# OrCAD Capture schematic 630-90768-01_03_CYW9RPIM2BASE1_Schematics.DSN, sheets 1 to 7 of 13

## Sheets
1 08. USB-UART Bridge: size B; title: CYW9RPIM2BASE1; rev: 3.0; note: 630-90768-01
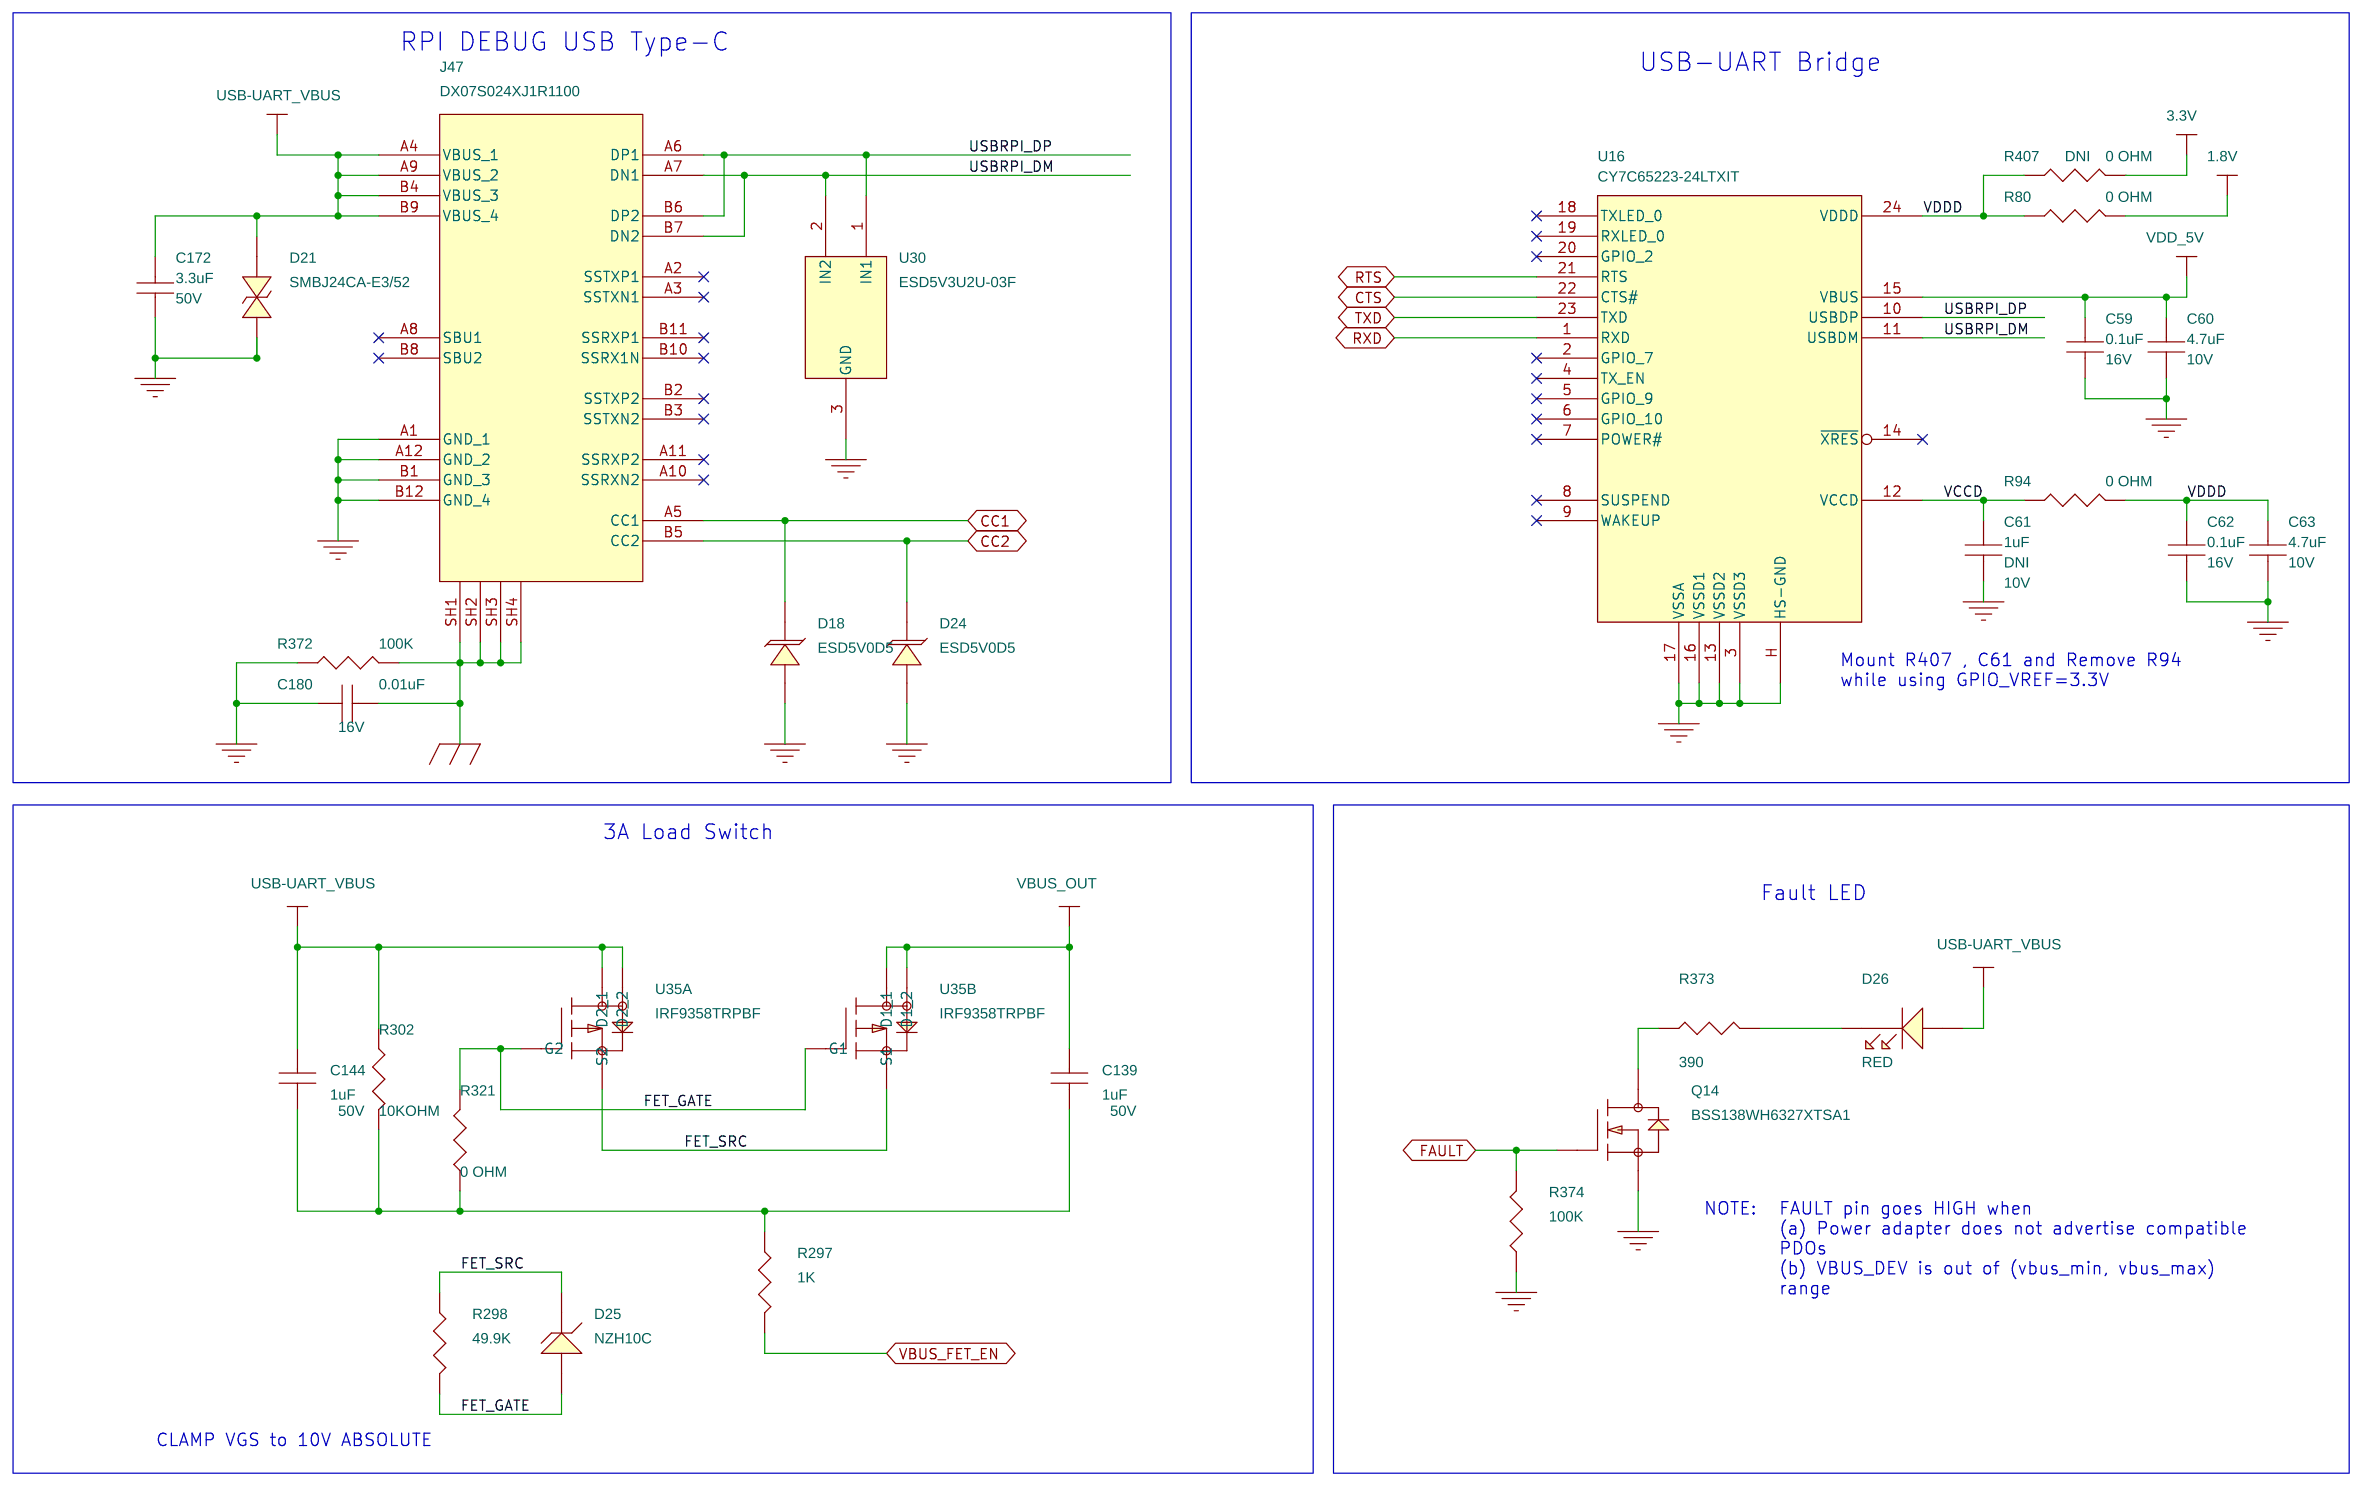
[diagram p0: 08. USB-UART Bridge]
2 09. Type-C BCR Controller: size B
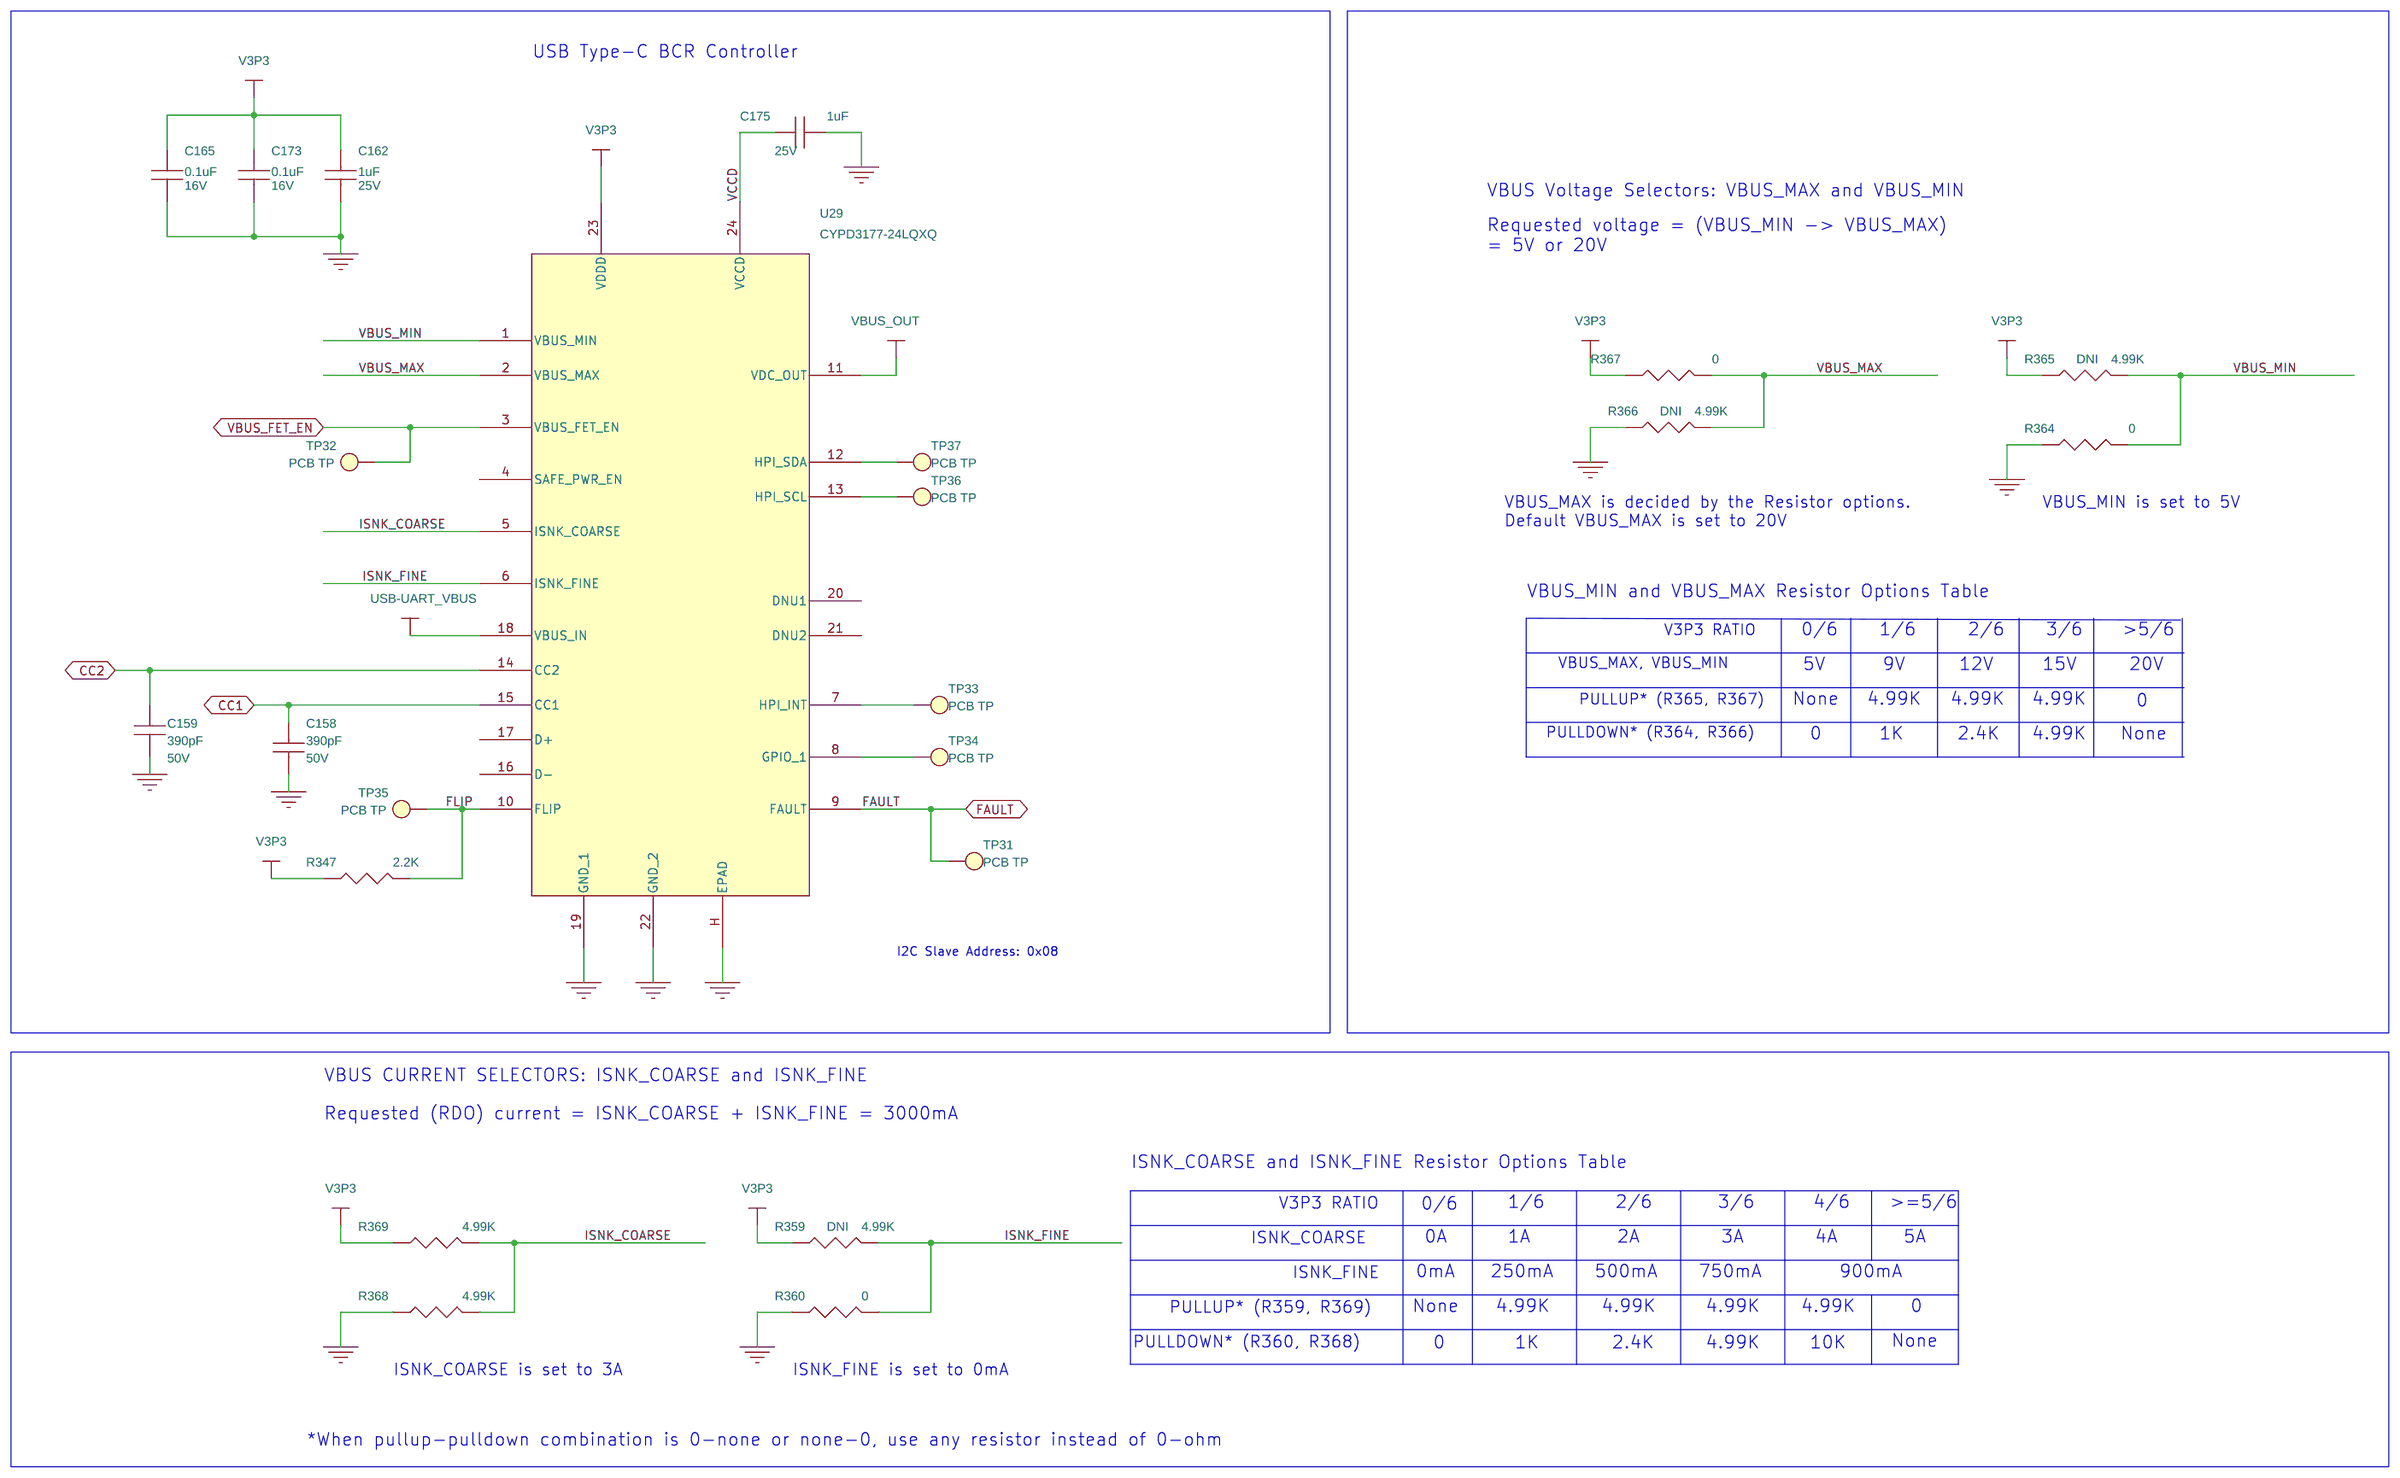
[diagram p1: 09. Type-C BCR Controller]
3 10. Audio Out: size A4
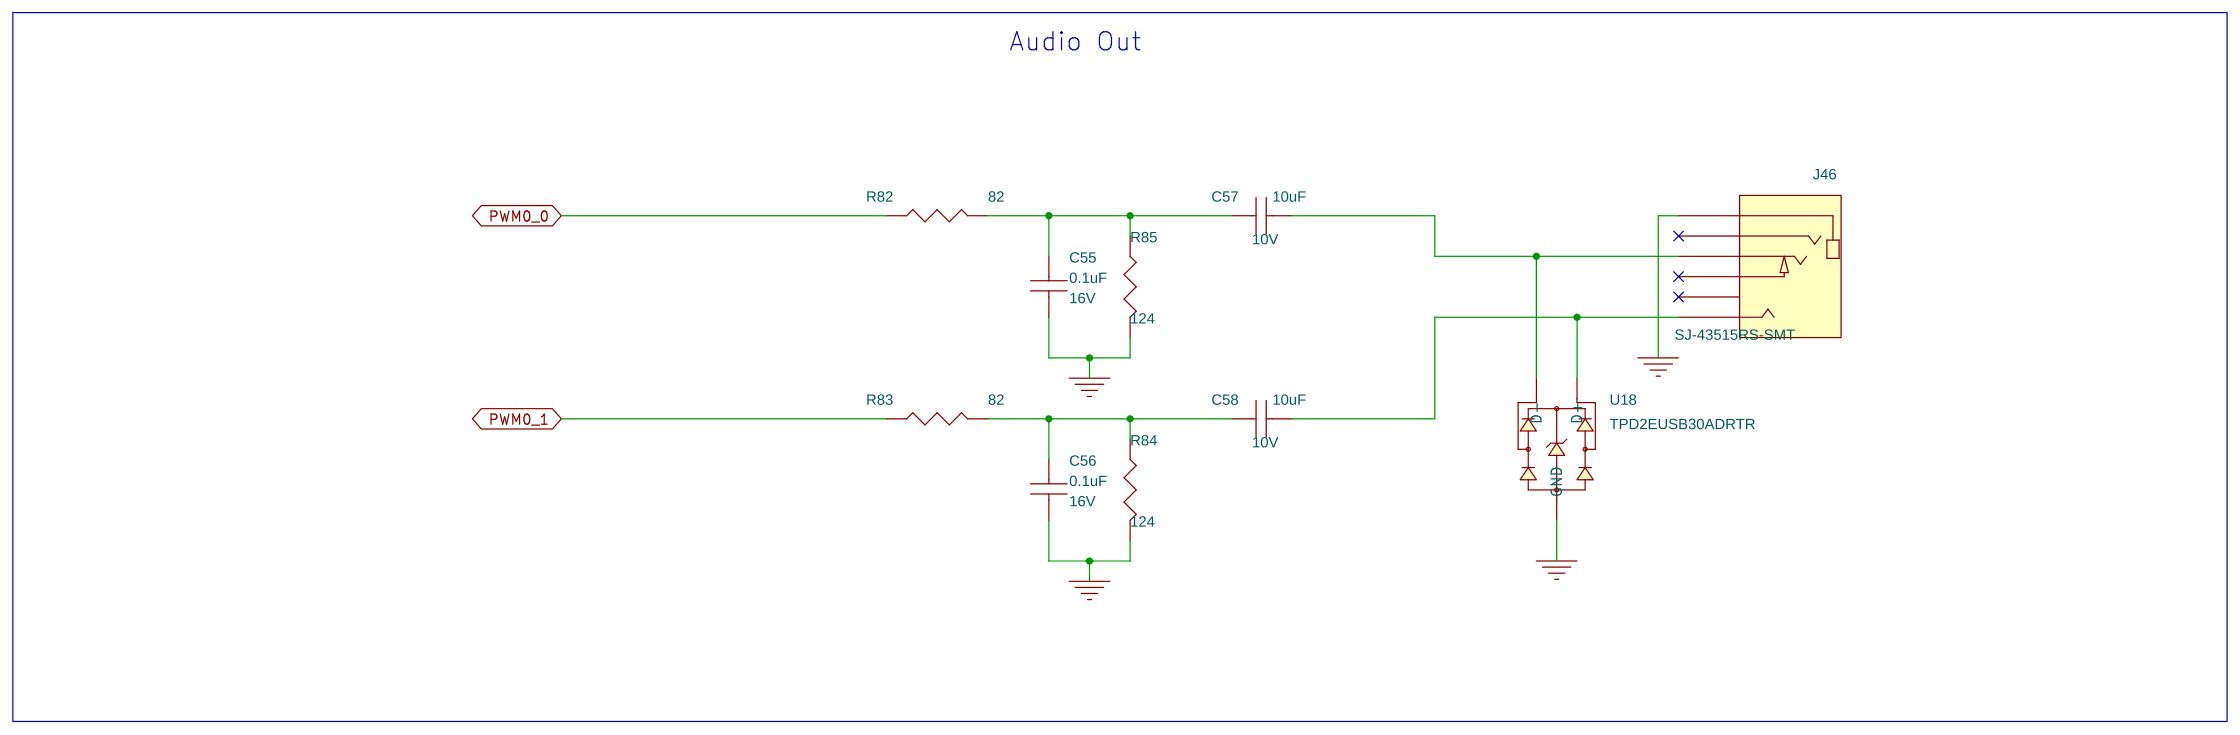
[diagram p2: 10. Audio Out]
4 01. Title Page
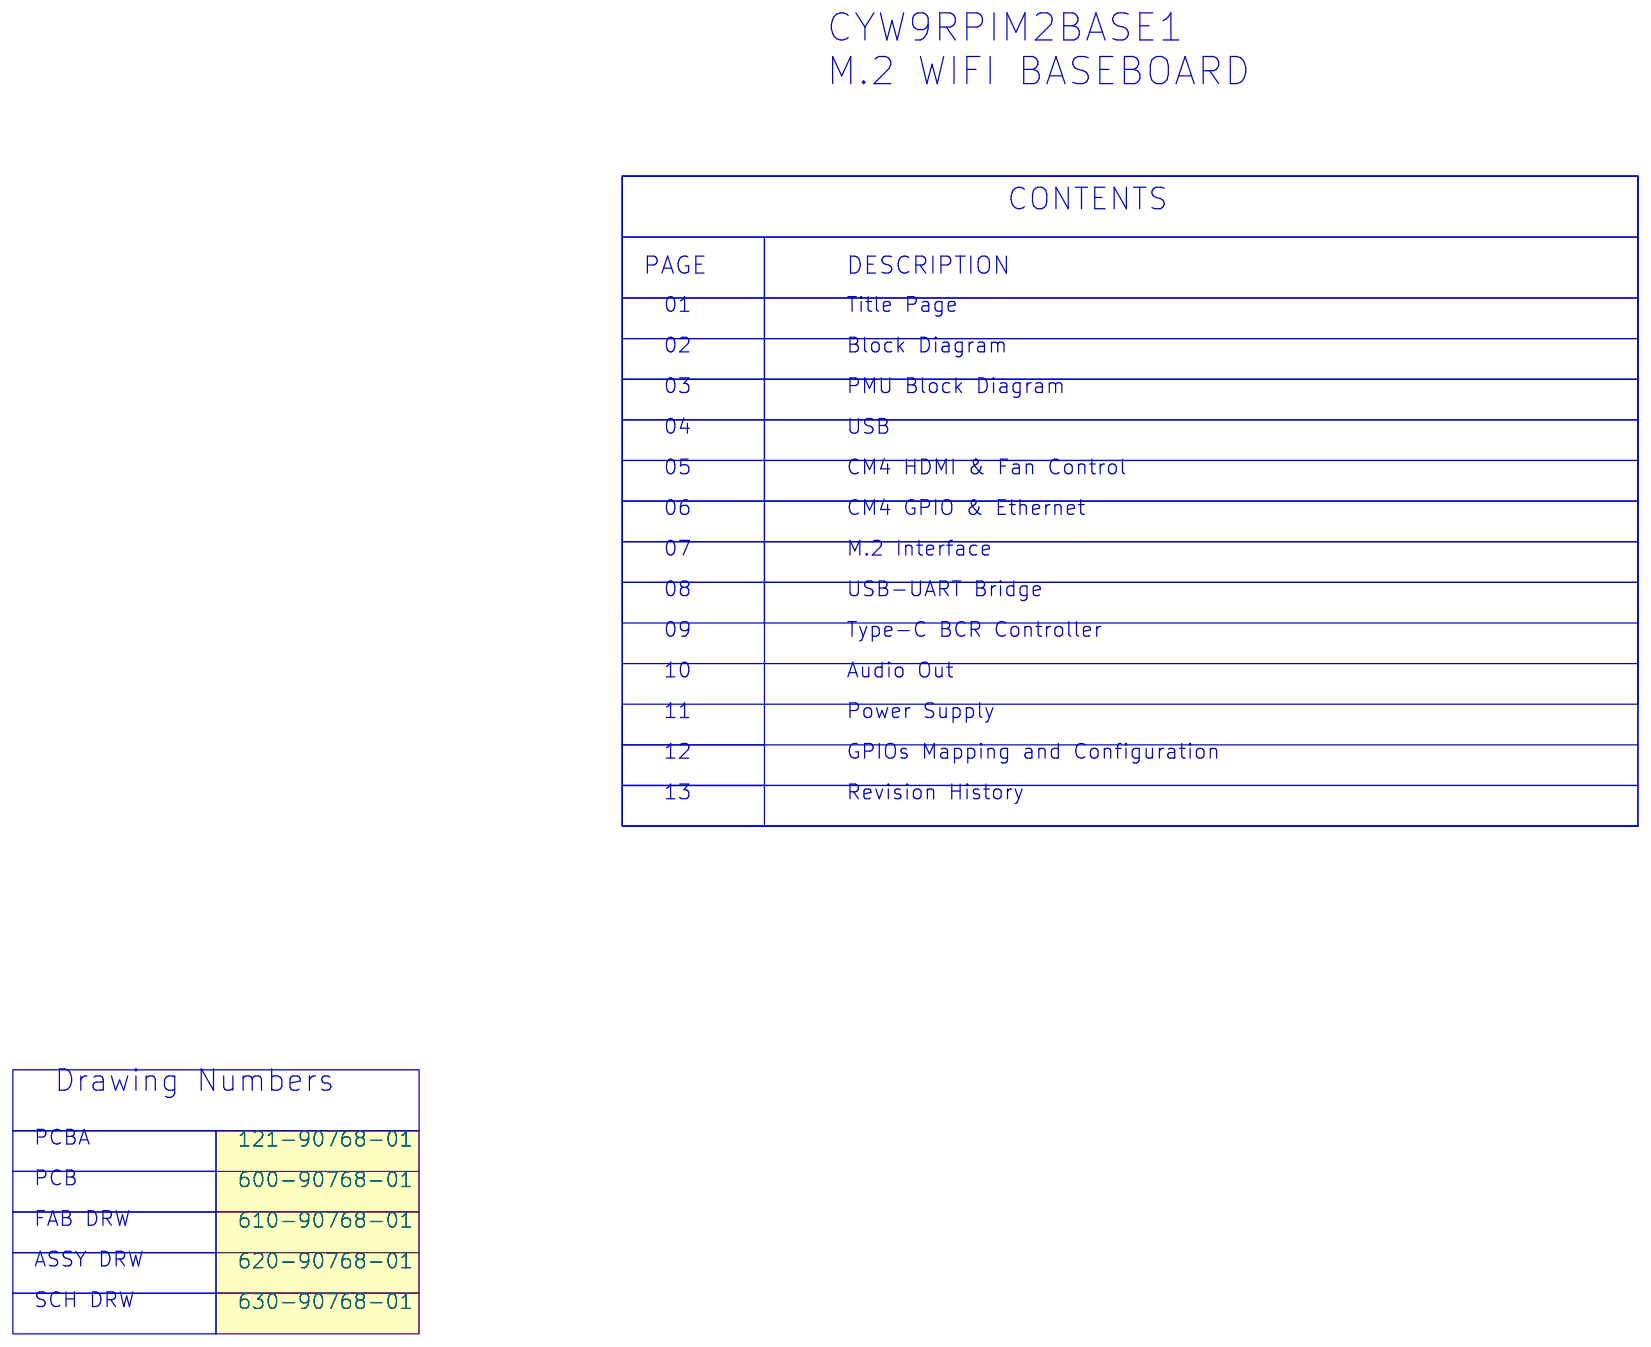
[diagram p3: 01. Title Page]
5 02. Block Diagram
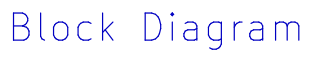
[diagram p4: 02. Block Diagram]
6 03. Power Block Diagram
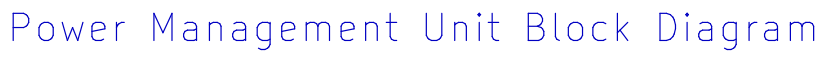
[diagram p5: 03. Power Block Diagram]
7 04. USB: size B
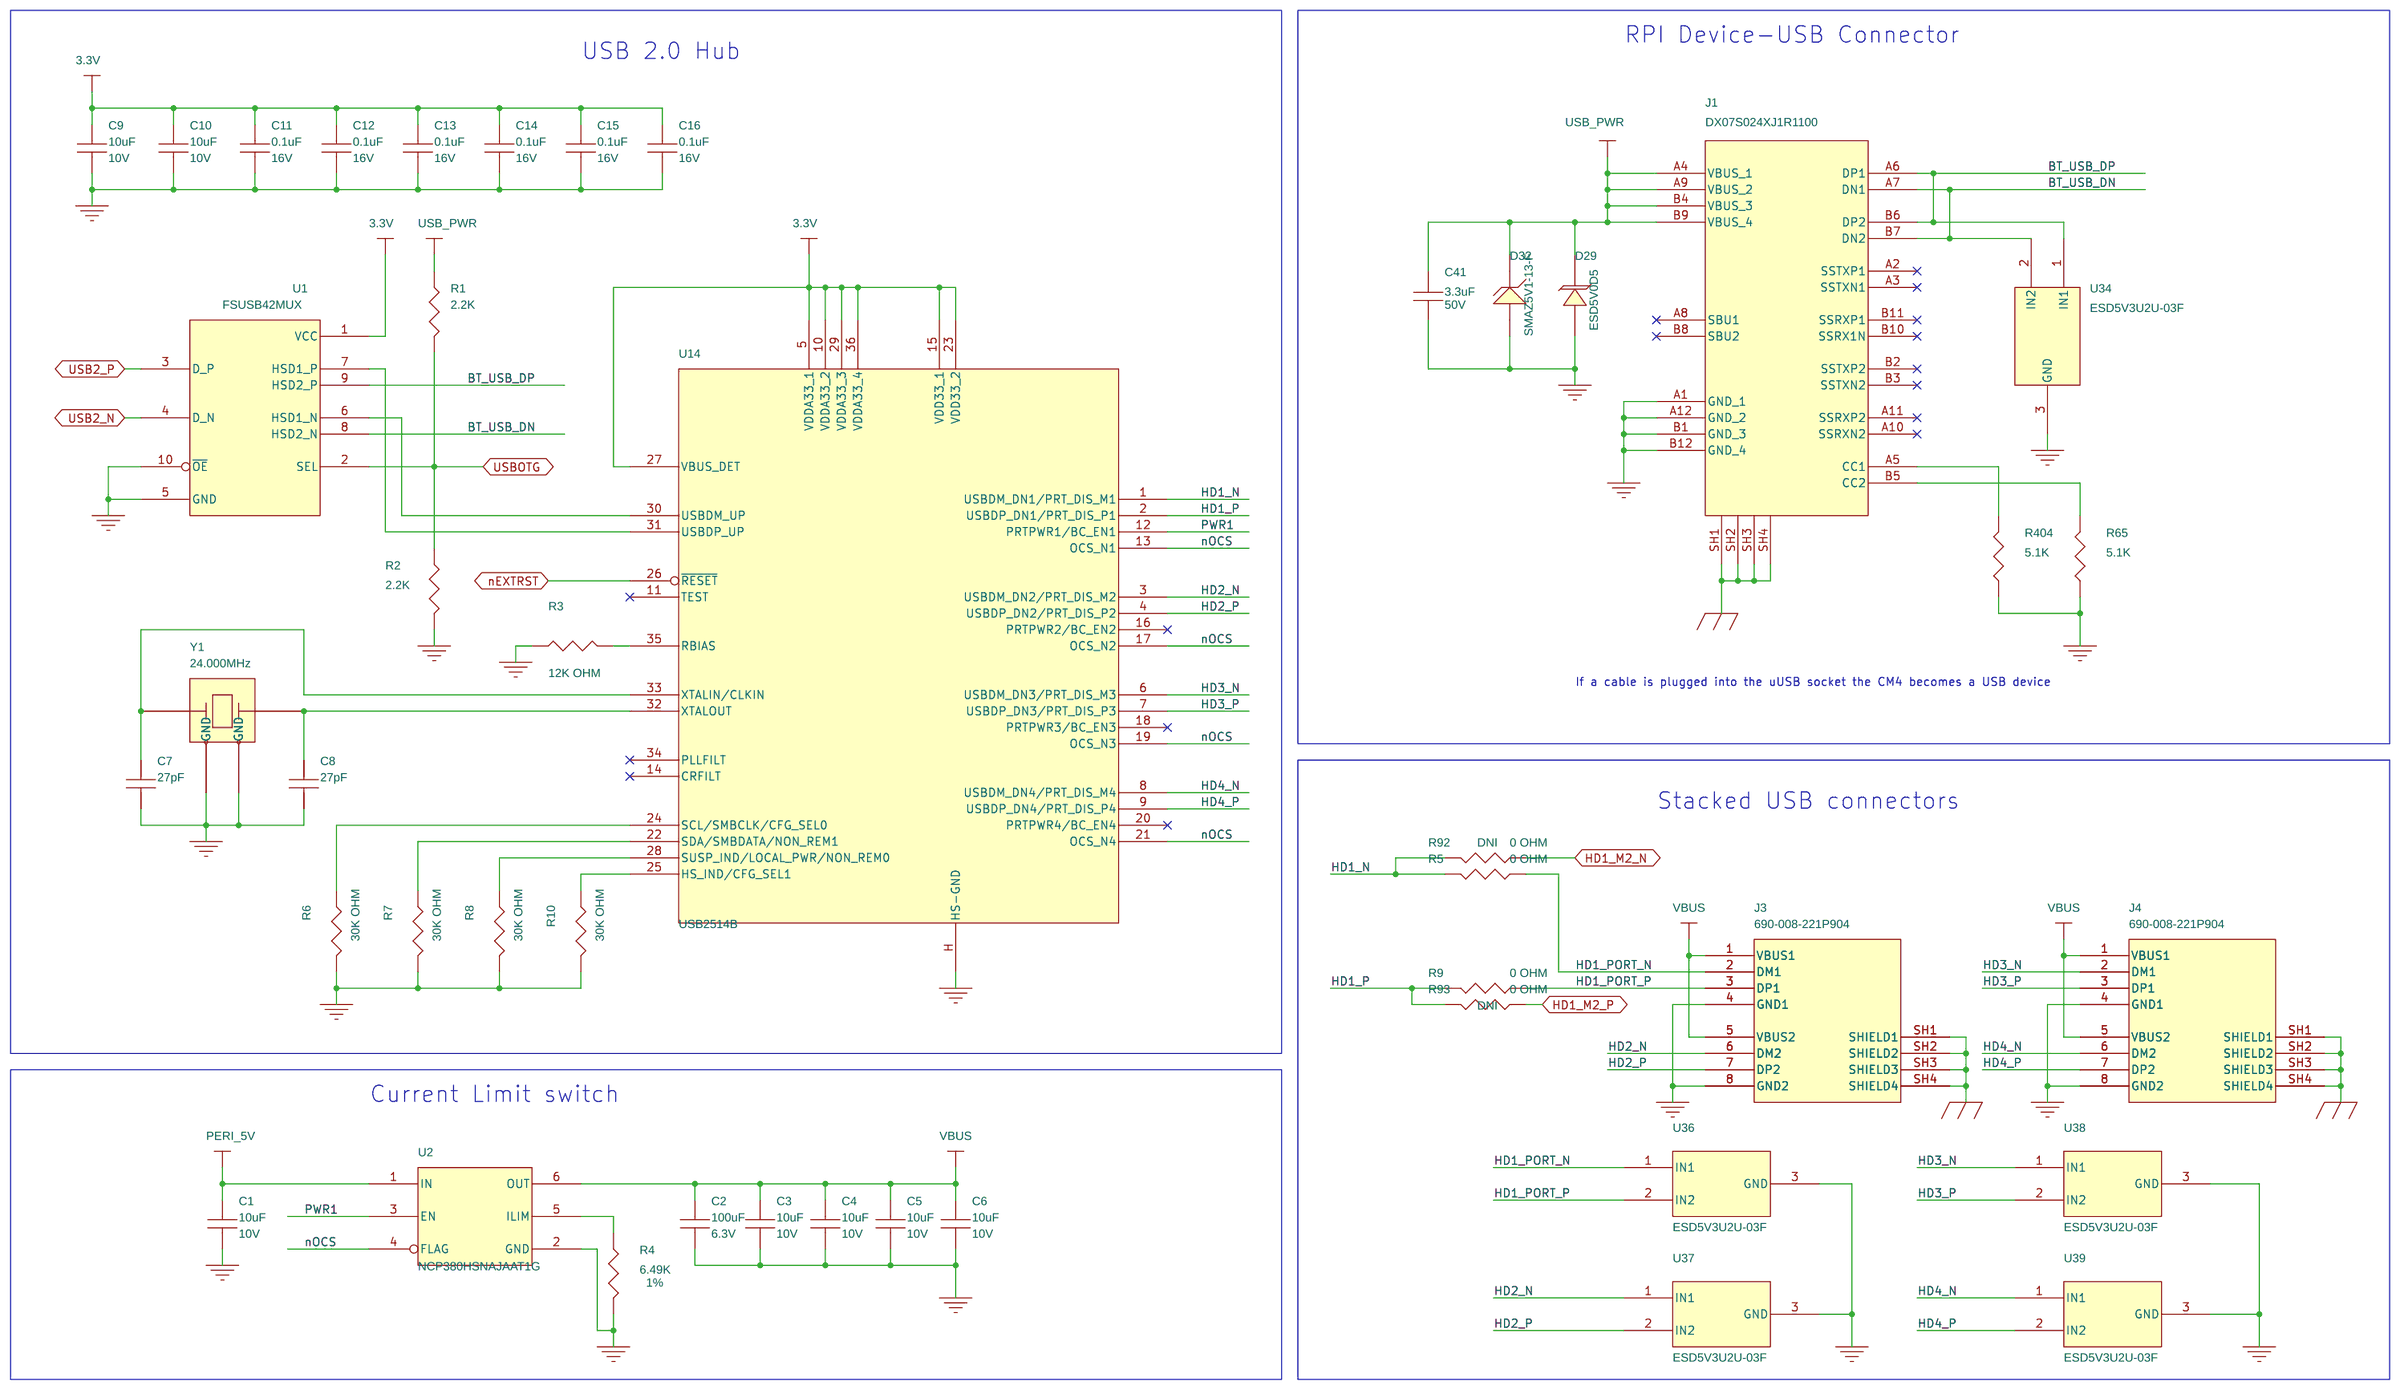
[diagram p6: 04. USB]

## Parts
sheet 01. Title Page
ACC1  121-90768-01  [TBD]
ACC2  600-90768-01  [TBD]
ACC3  610-90768-01  [TBD]
ACC4  620-90768-01  [TBD]
ACC5  630-90768-01  [TBD]
sheet 04. USB
C1  10uF  [CAPC1005_IS0402Q]
C2  100uF  [CAPC3216_IS1206N]
C3  10uF  [CAPC1005_IS0402Q]
C4  10uF  [CAPC1005_IS0402Q]
C5  10uF  [CAPC1005_IS0402Q]
C6  10uF  [CAPC1005_IS0402Q]
C7  27pF  [CAPC1005_IS0402Q]
C8  27pF  [CAPC1005_IS0402Q]
C9  10uF  [CAPC1005_IS0402Q]
C10  10uF  [CAPC1005_IS0402Q]
C11  0.1uF  [CAPC1005_IS0402Q]
C12  0.1uF  [CAPC1005_IS0402Q]
C13  0.1uF  [CAPC1005_IS0402Q]
C14  0.1uF  [CAPC1005_IS0402Q]
C15  0.1uF  [CAPC1005_IS0402Q]
C16  0.1uF  [CAPC1005_IS0402Q]
C41  3.3uF  [CAPC3225_1210N_H190]
D29  ESD5V0D5  [sodfl1608X77N]
D32  SMAZ5V1-13-F  [DIOM4326_SMA_DO214ACN]
J1  DX07S024XJ1R1100  [JAE_DX07S024XJ1]
J3  690-008-221P904  [usb-8p-690-008-221-904]
J4  690-008-221P904  [usb-8p-690-008-221-904]
R1  2.2K  [RESC1005_IS0402Q]
R2  2.2K  [RESC1005_IS0402Q]
R3  12K OHM  [RESC1005_IS0402Q]
R4  6.49K  [RESC1005_IS0402Q]
R5  0 OHM  [RESC1005_IS0402Q]
R6  30K OHM  [RESC1005_IS0402Q]
R7  30K OHM  [RESC1005_IS0402Q]
R8  30K OHM  [RESC1005_IS0402Q]
R9  0 OHM  [RESC1005_IS0402Q]
R10  30K OHM  [RESC1005_IS0402Q]
R65  5.1K  [RESC1005_IS0402Q]
R92  0 OHM  [RESC1005_IS0402Q]
R93  0 OHM  [RESC1005_IS0402Q]
R404  5.1K  [RESC1005_IS0402Q]
U1  FSUSB42MUX  [msop50P490x300-10N]
U2  NCP380HSNAJAAT1G  [tsop095p275_6_300]
U14  USB2514B  [qfn50p600x600_36_hs370]
U34  ESD5V3U2U-03F  [SOTFL40P120X59-3N]
U36  ESD5V3U2U-03F  [SOTFL40P120X59-3N]
U37  ESD5V3U2U-03F  [SOTFL40P120X59-3N]
U38  ESD5V3U2U-03F  [SOTFL40P120X59-3N]
U39  ESD5V3U2U-03F  [SOTFL40P120X59-3N]
Y1  24.000MHz  [XTALS4_3M2X2M5]
sheet 08. USB-UART Bridge
C59  0.1uF  [CAPC1005_IS0402Q]
C60  4.7uF  [CAPC1005_IS0402Q]
C61  1uF  [CAPC1005_IS0402Q]
C62  0.1uF  [CAPC1005_IS0402Q]
C63  4.7uF  [CAPC1005_IS0402Q]
C139  1uF  [CAPC1608_IS0603Q]
C144  1uF  [CAPC1608_IS0603Q]
C172  3.3uF  [CAPC3225_1210N_H190]
C180  0.01uF  [CAPC1005_IS0402Q]
D18  ESD5V0D5  [sodfl1608X77N]
D21  SMBJ24CA-E3/52  [DIOM5336X265N]
D24  ESD5V0D5  [sodfl1608X77N]
D25  NZH10C  [sodfl3516x120n]
D26  RED  [LEDC1608Q]
J47  DX07S024XJ1R1100  [JAE_DX07S024XJ1]
Q14  BSS138WH6327XTSA1  [SOT65P210X110-3N]
R80  0 OHM  [RESC1005_IS0402Q]
R94  0 OHM  [RESC1005_IS0402Q]
R297  1K  [RESC1005_IS0402Q]
R298  49.9K  [RESC1005_IS0402Q]
R302  10KOHM  [RESC1005_IS0402Q]
R321  0 OHM  [RESC1005_IS0402Q]
R372  100K  [RESC1005_IS0402Q]
R373  390  [RESC1005_IS0402Q]
R374  100K  [RESC1005_IS0402Q]
R407  0 OHM  [RESC1005_IS0402Q]
U16  CY7C65223-24LTXIT  [qfn50p400x400x55_24_hs265n]
U30  ESD5V3U2U-03F  [SOTFL40P120X59-3N]
U35  IRF9358TRPBF  [SOIC127P600X175-8N]  (sections A,B)
sheet 09. Type-C BCR Controller
C158  390pF  [CAPC1005_0402N]
C159  390pF  [CAPC1005_0402N]
C162  1uF  [CAPC1608_IS0603Q]
C165  0.1uF  [CAPC1005_IS0402Q]
C173  0.1uF  [CAPC1005_IS0402Q]
C175  1uF  [CAPC1608_IS0603Q]
R347  2.2K  [RESC1005_IS0402Q]
R359  4.99K  [RESC1608_IS0603Q]
R360  0  [RESC1608_IS0603Q]
R364  0  [RESC1608_IS0603Q]
R365  4.99K  [RESC1608_IS0603Q]
R366  4.99K  [RESC1608_IS0603Q]
R367  0  [RESC1608_IS0603Q]
R368  4.99K  [RESC1608_IS0603Q]
R369  4.99K  [RESC1608_IS0603Q]
TP31  PCB TP  [tp102c]
TP32  PCB TP  [tp102c]
TP33  PCB TP  [tp102c]
TP34  PCB TP  [tp102c]
TP35  PCB TP  [tp102c]
TP36  PCB TP  [tp102c]
TP37  PCB TP  [tp102c]
U29  CYPD3177-24LQXQ  [QFN50P400x400_24_H280N]
sheet 10. Audio Out
C55  0.1uF  [CAPC1005_IS0402Q]
C56  0.1uF  [CAPC1005_IS0402Q]
C57  10uF  [CAPC1005_IS0402Q]
C58  10uF  [CAPC1005_IS0402Q]
J46  SJ-43515RS-SMT  [jack-earphone-aci]
R82  82  [RESC1608_IS0603Q]
R83  82  [RESC1608_IS0603Q]
R84  124  [RESC1005_IS0402Q]
R85  124  [RESC1005_IS0402Q]
U18  TPD2EUSB30ADRTR  [SOT3_TPD2EUSB30ADRT]

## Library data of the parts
ACC1 = PCB: ASSY, PCBA, CYW9RPIM2BASE1; Asm_Instruction: No Load; Cy_part#: 121-60553-01; DNI: DNI; Manufacturer: Cypress Approved CM; Manufacturer_PN: -NA-; Mfr_Name: Cypress Approved CM; Mfr_Part#: -NA-; Mfr_Part_Number: -NA-
ACC2 = PCB: PCB, BARE, CYW9RPIM2BASE1; Asm_Instruction: No Load; Cy_part#: 600-60553-01; DNI: DNI; Manufacturer: Cypress Approved CM; Manufacturer_PN: -NA-; Mfr_Name: Cypress Approved CM; Mfr_Part#: -NA-; Mfr_Part_Number: -NA-
ACC3 = PCB: DRW, FABRICATION DRAWING, CYW9RPIM2BASE1; Asm_Instruction: No Load; Cy_part#: 610-60553-01; DNI: DNI; Manufacturer: -NA-; Manufacturer_PN: -NA-; Mfr_Name: -NA-; Mfr_Part#: -NA-; Mfr_Part_Number: -NA-
ACC4 = PCB: DRW, ASSEMBLY DRAWING, CYW9RPIM2BASE1; Asm_Instruction: No Load; Cy_part#: 620-60553-01; DNI: DNI; Manufacturer: -NA-; Manufacturer_PN: -NA-; Mfr_Name: -NA-; Mfr_Part#: -NA-; Mfr_Part_Number: -NA-
ACC5 = PCB: DRW, SCHEMATIC DRAWING, CYW9RPIM2BASE1; Asm_Instruction: No Load; Cy_part#: 630-60553-01; DNI: DNI; Manufacturer: -NA-; Manufacturer_PN: -NA-; Mfr_Name: -NA-; Mfr_Part#: -NA-; Mfr_Part_Number: -NA-
C1 C3-C6 C9 C10 C57 C58 = CAP: CAP, CER, 0402, 10uF, 20%, 10V, X5R; Assembly Instructions: <Assembly Instructions>; BRCM PN: 548985-00; CYPN: 510-90884-01; Enviromental: RoHS; FPLIST: CAPC1005_IS0402Q,CAPC1005_IS0402N; PART TYPE: Ceramic Capacitor; Size: 0402; Status: APPROVED; TC: X5R; Tolerance: 20%; VOLTAGE: 10V; vendor_1: DARFON; vendor_2: Murata Electronics North America; vendor_3: Walsin; vendor_part_number_1: C1005X5R106MDTS; vendor_part_number_2: GRM155R61A106ME11D; vendor_part_number_3: 0402X106M100CT; Datasheet: \\shasdv005.infineon.com\CMU\CMU_ORCAD_CIS_LIB\CYPRESS_CIS_DATABASE\datasheet\S_CL05A106MP5NUNC.pdf
C2 = CAP: CAP, CER, 1206, 100uF, 20%, 6.3V, X5R; Assembly Instructions: <Assembly Instructions>; BRCM PN: 537294-00; CYPN: 510-91191-01; Enviromental: RoHS; PART TYPE: Ceramic Capacitor; Size: 1206; Status: APPROVED; TC: X5R; Tolerance: 20%; VOLTAGE: 6.3V; vendor_1: DARFON; vendor_2: Murata; vendor_3: Walsin; vendor_part_number_1: C3216X5R107MCPS; vendor_part_number_2: GRM31CR60J107ME39K; vendor_part_number_3: 1206X107M6R3CT; Datasheet: \\shasdv005.infineon.com\CMU\CMU_ORCAD_CIS_LIB\CYPRESS_CIS_DATABASE\datasheet\GRM31CR60J107ME39K.pdf
C7 C8 = CAP: CAP, CER, 0402, 27pF, 1%, 50V, C0G; Assembly Instructions: <Assembly Instructions>; CYPN: 510-90724-01; Enviromental: RoHS; FPLIST: CAPC1005_IS0402Q,CAPC1005_IS0402N; PART TYPE: Ceramic Capacitor; Size: 0402; Status: APPROVED; TC: C0G; Tolerance: 1%; VOLTAGE: 50V; vendor_1: DARFON; vendor_2: Murata; vendor_3: Walsin; vendor_part_number_1: C1005NP0270FGTS; vendor_part_number_2: GRM1555C1H270FA01D; vendor_part_number_3: 0402N270F500LT; Datasheet: \\shasdv005.infineon.com\CMU\CMU_ORCAD_CIS_LIB\CYPRESS_CIS_DATABASE\datasheet\C1005NP0270FGTS.rar
C11-C16 C55 C56 C59 C62 C165 C173 = CAP: CAP, CER, 0402, 0.1uF, 10%, 16V, X7R; Assembly Instructions: <Assembly Instructions>; BRCM PN: 520157-00; CYPN: 510-90749-01; Enviromental: RoHS; FPLIST: CAPC1005_IS0402Q,CAPC1005_IS0402N,capc1005_is0402q_HP; PART TYPE: Ceramic Capacitor; Size: 0402; Status: APPROVED; TC: X7R; Tolerance: 10%; VOLTAGE: 16V; vendor_1: DARFON; vendor_2: DARFON; vendor_3: Walsin; vendor_4: Samsung; vendor_5: Murata Electronics North America; vendor_part_number_1: C1005X7R104KETS; vendor_part_number_2: C1005X7R104KETA; vendor_part_number_3: 0402B104K160CT; vendor_part_number_4: CL05B104KO5NNNC; vendor_part_number_5: GRM155R71C104KA88D -NRND-; Datasheet: \\shasdv005.infineon.com\CMU\CMU_ORCAD_CIS_LIB\CYPRESS_CIS_DATABASE\datasheet\Murata_GRM155R71C104KA88D.pdf
C41 C172 = CAP: CAP, CER, 1210, 3.3uF, 10%, 50V, X7R, -55 to 125C, AEQ-200; Assembly Instructions: <Assembly Instructions>; Automotive: Automotive; CYPN: 510-91441-01; Enviromental: RoHS; PART TYPE: Ceramic Capacitor; Size: 1210; Status: APPROVED; TC: X7R; Tolerance: 10%; VOLTAGE: 50V; vendor_1: Kemet; vendor_part_number_1: C1210C335K5RACAUTO; Datasheet: \\shasdv005.infineon.com\CMU\CMU_ORCAD_CIS_LIB\CYPRESS_CIS_DATABASE\datasheet\C1210C335K5RACAUTO.pdf
D18 D24 D29 = DIO-TVS-ESD: DIO, TVS, UNIDIR, ESD PROTECTION, 5V, 18.6V, 174W, SOD-523; Assembly Instructions: <Assembly Instructions>; CYPN: 530-90211-01; Enviromental: RoHS; PART TYPE: TVS; Status: APPROVED; VOLTAGE: 5V; vendor_1: Micro Commercial Components; vendor_part_number_1: ESD5V0D5-TP; Datasheet: \\shasdv005.infineon.com\CMU\CMU_ORCAD_CIS_LIB\CYPRESS_CIS_DATABASE\datasheet\ESD5V0D5-TP.PDF
D32 = DIO-ZENER: DIO, ZNR, SMA, 5.1V, 100mA, 1W; Assembly Instructions: <Assembly Instructions>; BRCM PN: 541051-00; CYPN: 530-90156-01; Current: 100mA; Enviromental: RoHS; PART TYPE: ZENER; Status: APPROVED; VOLTAGE: 5.1V; vendor_1: Diodes Inc; Datasheet: \\shasdv005.infineon.com\CMU\CMU_ORCAD_CIS_LIB\CYPRESS_CIS_DATABASE\datasheet\SMAZ5V1-13-F.pdf
J1 J47 = CONN_USB_TYPEC-24P-4SH: CON, USB3.1, TYPE C, 24PIN, TOP MOUNT, R/A, HYBRID, -30 to 80C; Assembly Instructions: <Assembly Instructions>; CYPN: 720-90572-01; Enviromental: RoHS; PART TYPE: USB; Status: APPROVED; vendor_1: JAE Electronics; Datasheet: \\shasdv005.infineon.com\CMU\CMU_ORCAD_CIS_LIB\CYPRESS_CIS_DATABASE\datasheet\DX07S024XJ1R1100
J3 J4 = USB_TYPEA_2DECK_4SH_J: CONN, USB, TYPE A, RECEPTACLE, DOUBLE DECK, R/A, 8P, SHLD; Assembly Instructions: <Assembly Instructions>; CYPN: 720-90644-01; Enviromental: RoHS; PART TYPE: USB; Status: APPROVED; vendor_1: EDAC; Datasheet: \\shasdv005.infineon.com\CMU\CMU_ORCAD_CIS_LIB\CYPRESS_CIS_DATABASE\datasheet\690-008-221-904.pdf
R1 R2 R347 = RES: RES, THK, 0402, 2.2K OHM, 5%, 63mW; Assembly Instructions: <Assembly Instructions>; BRCM PN: 559975-00; CYPN: 500-90839-01; Enviromental: RoHS; FPLIST: RESC1005_IS0402Q,RESC1005_IS0402N; PART TYPE: THICK FILM; Size: 0402; Status: APPROVED; Tolerance: 5%; vendor_1: CYNTEC; vendor_2: KOA Speer Electronics; vendor_3: Panasonic-ECG; vendor_4: RALEC; vendor_5: VIKING TECH; vendor_6: Walsin; vendor_part_number_1: PFR05S-222-JNH; vendor_part_number_2: RK73B1ETTP222J; vendor_part_number_3: ERJ-2GEJ222X; vendor_part_number_4: RTT02222JTH; vendor_part_number_5: CR-02JL6---2K2AC; vendor_part_number_6: WR04X222 JTL
R3 = RES: RES, THK, 0402, 12K OHM, 1%, 63mW; Assembly Instructions: <Assembly Instructions>; CYPN: 500-90852-01; Enviromental: RoHS; FPLIST: RESC1005_IS0402Q,RESC1005_IS0402N; PART TYPE: THICK FILM; Size: 0402; Status: APPROVED; Tolerance: 1%; vendor_1: CYNTEC; vendor_2: RALEC; vendor_3: VIKING TECH; vendor_4: Walsin; vendor_5: Yageo America; vendor_part_number_1: PFR05S-1202-FNH; vendor_part_number_2: RTT021202FTH; vendor_part_number_3: CR-02FL6---12KAC; vendor_part_number_4: WR04X1202FTL; vendor_part_number_5: RC0402FR-0712KL; Datasheet: \\shasdv005.infineon.com\CMU\CMU_ORCAD_CIS_LIB\CYPRESS_CIS_DATABASE\datasheet\CR REV.C3-160715.pdf
R4 = RES: RES, THK, 0402, 6.49K, 1%, 63mW; Assembly Instructions: <Assembly Instructions>; CYPN: 500-91121-01; Enviromental: RoHS; FPLIST: RESC1005_IS0402Q,RESC1005_IS0402N; PART TYPE: THICK FILM; Size: 0402; Status: APPROVED; Tolerance: 1%; vendor_1: CYNTEC; vendor_2: VIKING TECH; vendor_3: Walsin; vendor_4: Yageo America; vendor_part_number_1: RR0510S-6491-FNH; vendor_part_number_2: CR-02FL6--6K49AC; vendor_part_number_3: WR04X6491FTL; vendor_part_number_4: RC0402FR-076K49L; Datasheet: \\shasdv005.infineon.com\CMU\CMU_ORCAD_CIS_LIB\CYPRESS_CIS_DATABASE\datasheet\RR0510S-6491-FNH.pdf
R5 R9 R80 R94 R321 = RES: RES, THK, 0402, 0 OHM, 63mW; Assembly Instructions: <Assembly Instructions>; BRCM PN: 500225-00; CYPN: 500-90842-01; Enviromental: RoHS; FPLIST: RESC1005_IS0402Q,RESC1005_IS0402N; PART TYPE: THICK FILM; Size: 0402; Status: APPROVED; Tolerance: 5%; vendor_1: Walsin; vendor_2: CYNTEC; vendor_3: KOA Speer Electronics; vendor_4: Panasonic-ECG; vendor_5: VIKING TECH; vendor_6: Yageo America; vendor_part_number_1: WR04X000 PTL; vendor_part_number_2: PFR05X-000-XNH; vendor_part_number_3: RK73Z1ETQTP; vendor_part_number_4: ERJ-2GE0R00X; vendor_part_number_5: CR-02JL6----0RAC; vendor_part_number_6: RC0402JR-070RL
R6-R8 R10 = RES: RES, THK, 0402, 30K OHM, 5%, 1/16W; Assembly Instructions: <Assembly Instructions>; CYPN: 500-91135-01; Enviromental: RoHS; FPLIST: RESC1005_IS0402Q,RESC1005_IS0402N; PART TYPE: THICK FILM; Size: 0402; Status: APPROVED; Tolerance: 5%; vendor_1: VIKING TECH; vendor_2: Walsin; vendor_part_number_1: CR-02JL6---30KAC; vendor_part_number_2: WR04X303 JTL; Datasheet: \\shasdv005.infineon.com\CMU\CMU_ORCAD_CIS_LIB\CYPRESS_CIS_DATABASE\datasheet\cr.pdf
R65 R404 = RES: RES, THK, 0402, 5.1K OHM, 5%, 63mW; Assembly Instructions: <Assembly Instructions>; CYPN: 500-90861-01; Enviromental: RoHS; FPLIST: RESC1005_IS0402Q,RESC1005_IS0402N; PART TYPE: THICK FILM; Size: 0402; Status: APPROVED; Tolerance: 5%; vendor_1: CYNTEC; vendor_2: VIKING TECH; vendor_3: Walsin; vendor_part_number_1: PFR05S-512-JNH; vendor_part_number_2: CR-02JL6---5K1AC; vendor_part_number_3: WR04X512 JTL
R92 R93 R407 = RES: RES, THK, 0402, 0 OHM, 63mW; Assembly Instructions: <Assembly Instructions>; BRCM PN: 500225-00; CYPN: 500-90842-01; DNI: DNI; Enviromental: RoHS; FPLIST: RESC1005_IS0402Q,RESC1005_IS0402N; PART TYPE: THICK FILM; Size: 0402; Status: APPROVED; Tolerance: 5%; vendor_1: Walsin; vendor_2: CYNTEC; vendor_3: KOA Speer Electronics; vendor_4: Panasonic-ECG; vendor_5: VIKING TECH; vendor_6: Yageo America; vendor_part_number_1: WR04X000 PTL; vendor_part_number_2: PFR05X-000-XNH; vendor_part_number_3: RK73Z1ETQTP; vendor_part_number_4: ERJ-2GE0R00X; vendor_part_number_5: CR-02JL6----0RAC; vendor_part_number_6: RC0402JR-070RL
U1 = FSUSB42MUX_MSOP10: IC, UART SWH, USE2.0, DPDT, LOW POWER, TWO PORT, HIGH SPEEED, MSOP-10; Assembly Instructions: <Assembly Instructions>; CYPN: 450-90671-01; Enviromental: RoHS; PART TYPE: SWITCH; Status: APPROVED; vendor_1: ON SEMICONDUCTOR; Datasheet: \\shasdv005.infineon.com\CMU\CMU_ORCAD_CIS_LIB\CYPRESS_CIS_DATABASE\datasheet\FSUSB42-D.PDF
U2 = NCP380_TSOP-6: IC, Adjustable Current-Limiting Power-Distribution Switch, 3.0/5.5V, 0.5/2.1A, TSOP-6; CYPN: 450-90571-01; Enviromental: RoHS; PART TYPE: SWITCH; Status: APPROVED; vendor_1: ON SEMICONDUCTOR; vendor_2: Diodes Inc; vendor_part_number_2: AP22653W6-7; Datasheet: \\shasdv005.infineon.com\CMU\CMU_ORCAD_CIS_LIB\CYPRESS_CIS_DATABASE\datasheet\NCP380-D.pdf
U14 = USB2514B_SQFN36: IC, USB 2.0 Hi-Speed Hub Controller, SQFN-36; Assembly Instructions: <Assembly Instructions>; CYPN: 450-90670-01; Enviromental: RoHS; PART TYPE: USB; Status: APPROVED; vendor_1: MICROCHIP; vendor_part_number_1: USB2514B-I/M2; Datasheet: \\shasdv005.infineon.com\CMU\CMU_ORCAD_CIS_LIB\CYPRESS_CIS_DATABASE\datasheet\USB2514B.pdf
U30 U34 U36-U39 = ESD5V3U2U-03F: DIO, ULTRA LOW ESD PROTECTION, 5.3V, 2-Lines, UNI-DIR, +/-20KV, SOT-723; Assembly Instructions: <Assembly Instructions>; CYPN: 530-90212-01; Enviromental: RoHS; PART TYPE: TVS; Status: APPROVED; VOLTAGE: 5.3V; vendor_1: Infineon Technologies; Datasheet: \\shasdv005.infineon.com\CMU\CMU_ORCAD_CIS_LIB\CYPRESS_CIS_DATABASE\datasheet\ESD5V3U2U-03F.pdf
Y1 = XTAL-1G3G: XTAL, FXD, SMT, 24.000MHz, 10/10PPM, 8pF, FUND, 3.2x2.5x0.8mm; Assembly Instructions: <Assembly Instructions>; BRCM PN: 559320-00; CYPN: 542-90071-01; Enviromental: RoHS; PART TYPE: CRYSTAL; Status: APPROVED; vendor_1: TXC CORPORATION; vendor_part_number_1: 7V24070013; Datasheet: \\shasdv005.infineon.com\CMU\CMU_ORCAD_CIS_LIB\CYPRESS_CIS_DATABASE\datasheet\TXC 7V24070013.pdf
C60 C63 = CAP: CAP, CER, 0402, 4.7uF, 20%, 10V, X5R For CYW943907AEVAL1F only; Assembly Instructions: <Assembly Instructions>; BRCM PN: 548988-00; CYPN: 510-90731-01; Enviromental: RoHS; FPLIST: CAPC1005_IS0402Q,CAPC1005_IS0402N; PART TYPE: Ceramic Capacitor; Size: 0402; Status: APPROVED; TC: X5R; Tolerance: 20%; VOLTAGE: 10V; vendor_1: DARFON; vendor_2: Murata; vendor_3: TDK Corporation; vendor_4: Walsin; vendor_part_number_1: C1005X5R475MDTS; vendor_part_number_2: GRM155R61A475MEAA; vendor_part_number_3: C1005X5R1A475M050BC; vendor_part_number_4: 0402X475M100CT; Datasheet: \\shasdv005.infineon.com\CMU\CMU_ORCAD_CIS_LIB\CYPRESS_CIS_DATABASE\datasheet\C1005X5R1A475M050BC.pdf
C61 = CAP: CAP, CER, 0402, 1uF, 10%, 10V, X5R; Assembly Instructions: <Assembly Instructions>; CYPN: 510-90732-01; DNI: DNI; Enviromental: RoHS; FPLIST: CAPC1005_IS0402Q,CAPC1005_IS0402N; PART TYPE: Ceramic Capacitor; Size: 0402; Status: APPROVED; TC: X5R; Tolerance: 10%; VOLTAGE: 10V; vendor_1: DARFON; vendor_2: Murata; vendor_3: Walsin; vendor_part_number_1: C1005X5R105KDT; vendor_part_number_2: GRM155R61A105KE15D -EOL-; vendor_part_number_3: 0402X105K100CT; Datasheet: \\shasdv005.infineon.com\CMU\CMU_ORCAD_CIS_LIB\CYPRESS_CIS_DATABASE\datasheet\Taiyo_LMK105BJ105KV-F.pdf
C139 C144 = CAP: CAP, CER, 0603, 1uF, 10%, 50V, X5R; Assembly Instructions: <Assembly Instructions>; BRCM PN: 548153-00; CYPN: 510-90947-01; Enviromental: RoHS; FPLIST: CAPC1608_IS0603Q,CAPC1608_IS0603N; PART TYPE: Ceramic Capacitor; Size: 0603; Status: APPROVED; TC: X5R; Tolerance: 10%; VOLTAGE: 50V; vendor_1: Taiyo Yuden; vendor_part_number_1: UMK107BJ105KA-T; Datasheet: \\shasdv005.infineon.com\CMU\CMU_ORCAD_CIS_LIB\CYPRESS_CIS_DATABASE\datasheet\UMK107BJ105KA-T_SS.pdf
C180 = CAP: CAP, CER, 0402, 0.01uF, 10%, 16V, X7R; Assembly Instructions: <Assembly Instructions>; BRCM PN: 520156-00; CYPN: 510-90736-01; Enviromental: RoHS; FPLIST: CAPC1005_IS0402Q,CAPC1005_IS0402N; PART TYPE: Ceramic Capacitor; Size: 0402; Status: APPROVED; TC: X7R; Tolerance: 10%; VOLTAGE: 16V; vendor_1: DARFON; vendor_2: Murata; vendor_3: Samsung; vendor_4: Taiyo Yuden; vendor_5: Walsin; vendor_6: Murata; vendor_7: TDK Corporation; vendor_part_number_1: C1005X7R103KETS; vendor_part_number_2: GRM155R71C103KA01D; vendor_part_number_3: CL05B103KO5NNNC; vendor_part_number_4: EMK105BJ103KV-F; vendor_part_number_5: 0402B103K160CT; vendor_part_number_6: GRM155R71E103KA01D; vendor_part_number_7: C1005X7R1C103K050BA; Datasheet: \\shasdv005.infineon.com\CMU\CMU_ORCAD_CIS_LIB\CYPRESS_CIS_DATABASE\datasheet\Murata_GRM155R71C103KA01D.pdf
D21 = DIO-TVS-BIPOLAR: DIO, TVS DIODE, BI-DIR, 24VWM, 38.9VC, 15.4A, 600W, DO-214AA, AEC-Q101; Assembly Instructions: <Assembly Instructions>; Automotive: Automotive; CYPN: 530-90208-01; Current: 15.4A; Enviromental: RoHS; PART TYPE: TVS; Status: APPROVED; VOLTAGE: 38.9V; vendor_1: VISHAY; Datasheet: \\shasdv005.infineon.com\CMU\CMU_ORCAD_CIS_LIB\CYPRESS_CIS_DATABASE\datasheet\SMBJ24CA-E3_52.pdf
D25 = DIO-ZENER: DIO, ZENER, 10V, 20mA, 0.5W, SOD-123F; Assembly Instructions: <Assembly Instructions>; CYPN: 530-90209-01; Enviromental: RoHS; PART TYPE: ZENER; Status: APPROVED; VOLTAGE: 10V; vendor_1: Nexperia; vendor_part_number_1: NZH10C,115; Datasheet: \\shasdv005.infineon.com\CMU\CMU_ORCAD_CIS_LIB\CYPRESS_CIS_DATABASE\datasheet\NZH10C,115.pdf
D26 = DIO-LED: LED, 0603, 2.2V, 30mA, RED, STR, 1.8mcd, 130DEG; Assembly Instructions: <Assembly Instructions>; BRCM PN: 534363-00; CYPN: 530-90157-01; Current: 30mA; Enviromental: RoHS; PART TYPE: LED; Status: APPROVED; VOLTAGE: 2.2V; vendor_1: Lite On, Inc; vendor_2: Broadcom; vendor_part_number_1: LTST-C193KRKT-2A; vendor_part_number_2: QSMC-C133; Datasheet: \\shasdv005.infineon.com\CMU\CMU_ORCAD_CIS_LIB\CYPRESS_CIS_DATABASE\datasheet\QSMC-C133.rar
Q14 = FET-MOS-N: FET, MOSFET, N-CH, 60V, 0.28A, 0.5W, SOT323-3, AEC-Q101, -55 to 150C; Assembly Instructions: <Assembly Instructions>; Automotive: Automotive; CYPN: 532-90065-01; Enviromental: RoHS; PART TYPE: MOSFET-N; Status: APPROVED; vendor_1: Infineon Technologies; Datasheet: \\shasdv005.infineon.com\CMU\CMU_ORCAD_CIS_LIB\CYPRESS_CIS_DATABASE\datasheet\BSS138WH6327XTSA1.pdf
R297 = RES: RES, THK, 0402, 1K OHM, 1%, 63mW; Assembly Instructions: <Assembly Instructions>; CYPN: 500-90847-01; Enviromental: RoHS; PART TYPE: THICK FILM; Size: 0402; Status: APPROVED; Tolerance: 1%; vendor_1: Walsin; vendor_2: CYNTEC; vendor_3: CYNTEC; vendor_4: VIKING TECH; vendor_part_number_1: WR04X1001FTL; vendor_part_number_2: PFR05S-1001-FNH; vendor_part_number_3: PFR05S-102-FNH; vendor_part_number_4: CR-02FL6----1KAC; Datasheet: \\shasdv005.infineon.com\CMU\CMU_ORCAD_CIS_LIB\CYPRESS_CIS_DATABASE\datasheet\CR REV.C3-160715.pdf
R298 = RES: RES, THK, 0402, 49.9K OHM, 1%, 63mW; Assembly Instructions: <Assembly Instructions>; CYPN: 500-91131-01; Enviromental: RoHS; FPLIST: RESC1005_IS0402Q,RESC1005_IS0402N; PART TYPE: THICK FILM; Size: 0402; Status: APPROVED; Tolerance: 1%; vendor_1: VIKING TECH; vendor_2: Walsin; vendor_part_number_1: CR-02FL6--49K9AC; vendor_part_number_2: WR04X4992FTL; Datasheet: \\shasdv005.infineon.com\CMU\CMU_ORCAD_CIS_LIB\CYPRESS_CIS_DATABASE\datasheet\CR..AC REV.A.pdf
R302 = RES: RES, THK, 0402, 10K OHM, 5%, 63mW; Assembly Instructions: <Assembly Instructions>; BRCM PN: 500210-00; CYPN: 500-90845-01; Enviromental: RoHS; FPLIST: RESC1005_IS0402Q,RESC1005_IS0402N,RESC1005_IS0402Q_050RP; PART TYPE: THICK FILM; Size: 0402; Status: APPROVED; Tolerance: 5%; vendor_1: Walsin; vendor_2: CYNTEC; vendor_3: RALEC; vendor_4: TA-I/TYEE; vendor_5: VIKING TECH; vendor_6: Yageo America; vendor_part_number_1: WR04X103 JTL; vendor_part_number_2: PFR05S-103-JNH; vendor_part_number_3: RTT02103JTH; vendor_part_number_4: RM04JTN103; vendor_part_number_5: CR-02JL6---10KAC; vendor_part_number_6: RC0402JR-0710KL; Datasheet: \\shasdv005.infineon.com\CMU\CMU_ORCAD_CIS_LIB\CYPRESS_CIS_DATABASE\datasheet\CR..AC REV.A.pdf
R372 R374 = RES: RES, THK, 0402, 100K, 1%, 63mW; Assembly Instructions: <Assembly Instructions>; BRCM PN: 500559-00; CYPN: 500-90994-01; Enviromental: RoHS; FPLIST: RESC1005_IS0402Q,RESC1005_IS0402N; PART TYPE: THICK FILM; Size: 0402; Status: APPROVED; Tolerance: 1%; vendor_1: CYNTEC; vendor_10: Walsin; vendor_11: Walsin; vendor_12: Yageo America; vendor_13: Yageo America; vendor_2: KOA Speer Electronics; vendor_3: Panasonic-ECG; vendor_4: RALEC; vendor_5: RALEC; vendor_6: RALEC; vendor_7: TA-I/TYEE; vendor_8: VIKING TECH; vendor_9: Walsin; vendor_part_number_1: PFR05S-104-FNH; vendor_part_number_10: WR04X1003FGL; vendor_part_number_11: WR04X1003FQL; vendor_part_number_12: RC0402FR-07100KL; vendor_part_number_13: RC0402FR-13100KL; vendor_part_number_2: RK73H1ETQTP1003F; vendor_part_number_3: ERJ-2RKF1003X; vendor_part_number_4: RTT021003FTE; vendor_part_number_5: RTT021003FTH; vendor_part_number_6: RTT021003FTP; vendor_part_number_7: RM04FTN1003; vendor_part_number_8: CR-02FL6--100KAC; vendor_part_number_9: WR04X1003FTL; Datasheet: \\shasdv005.infineon.com\CMU\CMU_ORCAD_CIS_LIB\CYPRESS_CIS_DATABASE\datasheet\ERJ-2RKF1003X.pdf
R373 = RES: RES, THK, 0402, 390 OHM, 1%, 63mW; Assembly Instructions: <Assembly Instructions>; CYPN: 500-91276-01; Enviromental: RoHS; FPLIST: RESC1005_IS0402Q,RESC1005_IS0402N; PART TYPE: THICK FILM; Size: 0402; Status: APPROVED; Tolerance: 1%; vendor_1: CYNTEC; vendor_2: VIKING TECH; vendor_3: Walsin; vendor_part_number_1: PFR05S-391-FNH; vendor_part_number_2: CR-02FL6--390RAC; vendor_part_number_3: WR04X3900FTL; Datasheet: \\shasdv005.infineon.com\CMU\CMU_ORCAD_CIS_LIB\CYPRESS_CIS_DATABASE\datasheet\PFR05S-391-FNH.pdf
U16 = CY7C65223_QFN24: IC, USB-UART Single Channel Bridge Controller, USB2.0 full-speed 12mbps, 3mbps UART, 24-PIN QFN; Assembly Instructions: <Assembly Instructions>; CYPN: 450-90727-01; Enviromental: RoHS; PART TYPE: Miscellaneous; Status: APPROVED; vendor_1: Infineon Technologies; Datasheet: \\shasdv005.infineon.com\CMU\CMU_ORCAD_CIS_LIB\CYPRESS_CIS_DATABASE\datasheet\Infineon-CY7C65223-24LTXIT-DataSheet-v01_00-EN.pdf
U35 = MOSFET-P_DUAL_SO8: FET, MOSFET, DUAL P-CH, 30V, 9.2A, 2W, SO8, 4x5x1.75mm(MAX), -55 to 150C; Assembly Instructions: <Assembly Instructions>; CYPN: 532-90064-01; Enviromental: RoHS; PART TYPE: MOSFET-P; Status: APPROVED; vendor_1: Infineon Technologies; Datasheet: \\shasdv005.infineon.com\CMU\CMU_ORCAD_CIS_LIB\CYPRESS_CIS_DATABASE\datasheet\IRF9358TRPBF.pdf
C158 C159 = CAP: CAP, CER, 0402, 390pF, 10%, 50V, X7R, -55 to 125C; Assembly Instructions: <Assembly Instructions>; CYPN: 510-91444-01; Enviromental: RoHS; PART TYPE: Ceramic Capacitor; Size: 0402; Status: APPROVED; TC: X7R; Tolerance: 10%; VOLTAGE: 50V; vendor_1: Murata; vendor_part_number_1: GMD155R71H391KA01D; Datasheet: \\shasdv005.infineon.com\CMU\CMU_ORCAD_CIS_LIB\CYPRESS_CIS_DATABASE\datasheet\GMD155R71H391KA01#.pdf
C162 C175 = CAP: CAP, CER, 0603, 1uF, 20%, 25V, X5R; Assembly Instructions: <Assembly Instructions>; CYPN: 510-90762-01; Enviromental: RoHS; FPLIST: CAPC1608_IS0603Q,CAPC1608_IS0603N; PART TYPE: Ceramic Capacitor; Size: 0603; Status: APPROVED; TC: X5R; Tolerance: 20%; VOLTAGE: 25V; vendor_1: DARFON; vendor_2: Murata; vendor_3: Walsin; vendor_part_number_1: C1608X5R105MFTS; vendor_part_number_2: GRM188R61E105MAADD; vendor_part_number_3: 0603X105M250CT
R359 R365 R366 = RES: RES, THN, 0603, 4.99K, 0.1%, 0.1W; Assembly Instructions: <Assembly Instructions>; BRCM PN: 548183-00; CYPN: 500-91012-01; DNI: DNI; Enviromental: RoHS; FPLIST: RESC1608_IS0603Q,RESC1608_IS0603N; PART TYPE: THIN FILM; Size: 0603; Status: APPROVED; Tolerance: 0.1%; vendor_1: VISHAY; vendor_part_number_1: TNPW06034K99BEEA; Datasheet: \\shasdv005.infineon.com\CMU\CMU_ORCAD_CIS_LIB\CYPRESS_CIS_DATABASE\datasheet\TNPW06034K99BEEA.pdf
R360 R364 R367 = RES: RES, THK, 0603, 0 OHM, 0.1W; Assembly Instructions: <Assembly Instructions>; BRCM PN: 500300-00; CYPN: 500-90869-01; Enviromental: RoHS; FPLIST: RESC1608_IS0603Q,RESC1608_IS0603N; PART TYPE: THICK FILM; Size: 0603; Status: APPROVED; vendor_1: Walsin; vendor_2: KOA Speer Electronics; vendor_3: RALEC; vendor_4: VIKING TECH; vendor_5: Yageo America; vendor_part_number_1: WR06X000PTL; vendor_part_number_2: RK73Z1JTQTP; vendor_part_number_3: RTT03000JTP; vendor_part_number_4: CR-03JL7----0RAC; vendor_part_number_5: RC0603JR-070RL
R368 R369 = RES: RES, THN, 0603, 4.99K, 0.1%, 0.1W; Assembly Instructions: <Assembly Instructions>; BRCM PN: 548183-00; CYPN: 500-91012-01; Enviromental: RoHS; FPLIST: RESC1608_IS0603Q,RESC1608_IS0603N; PART TYPE: THIN FILM; Size: 0603; Status: APPROVED; Tolerance: 0.1%; vendor_1: VISHAY; vendor_part_number_1: TNPW06034K99BEEA; Datasheet: \\shasdv005.infineon.com\CMU\CMU_ORCAD_CIS_LIB\CYPRESS_CIS_DATABASE\datasheet\TNPW06034K99BEEA.pdf
TP31-TP37 = TP: TESTPOINT, PCB PAD, RND,1MM, SMT; Assembly Instructions: DNI; CYPN: TP-SMT-100-RND; PART TYPE: TEST-POINT
U29 = CYPD3177-24LQXQ_QFN24: IC, IFX CYPD3177-24LQXQ, USB, BCR, Type-C Controller, PD 3.0, 3V-24.5V, 24-QFN, -40 to 105C; Assembly Instructions: <Assembly Instructions>; CYPN: 410-90011-01; Enviromental: RoHS; PART TYPE: Microcontroller; Status: APPROVED; vendor_1: Infineon Technologies; vendor_part_number_1: CYPD3177-24LQXQT; Datasheet: \\shasdv005.infineon.com\CMU\CMU_ORCAD_CIS_LIB\CYPRESS_CIS_DATABASE\datasheet\CYPD3177-24LQXQ.pdf
J46 = CON-SJ-43515RS-SMT-J: CON, AUD JACK, SMT, F, R/A, 1PORT, 3.5mm, 5 POS; Assembly Instructions: <Assembly Instructions>; CYPN: 720-90614-01; Enviromental: RoHS; PART TYPE: AUDIO; Status: APPROVED; vendor_1: CUI Inc; vendor_part_number_1: SJ-43515RS-SMT-TR; Datasheet: \\shasdv005.infineon.com\CMU\CMU_ORCAD_CIS_LIB\CYPRESS_CIS_DATABASE\datasheet\SJ-43515RS-SMT-TR.pdf
R82 R83 = RES: RES, THK, 0603, 82, 5%, 100mW; Assembly Instructions: <Assembly Instructions>; BRCM PN: 522314-00; CYPN: 500-91037-01; Enviromental: RoHS; FPLIST: RESC1608_IS0603Q,RESC1608_IS0603N; PART TYPE: THICK FILM; Size: 0603; Status: APPROVED; Tolerance: 5%; vendor_1: KOA Speer Electronics; vendor_10: Yageo America; vendor_2: KOA Speer Electronics; vendor_3: KOA Speer Electronics; vendor_4: RALEC; vendor_5: RALEC; vendor_6: Walsin; vendor_7: Walsin; vendor_8: Walsin; vendor_9: Yageo America; vendor_part_number_1: RK73B1JTTD820J; vendor_part_number_10: RC0603JR-0782RL; vendor_part_number_2: RK73B1JTTP820J; vendor_part_number_3: RK73B1JTTDD820J; vendor_part_number_4: RTT03820JTP; vendor_part_number_5: RTT03820JTE; vendor_part_number_6: WR06X820JGL; vendor_part_number_7: WR06X820JQL; vendor_part_number_8: WR06X820JTL; vendor_part_number_9: RC0603JR-1382RL; Datasheet: \\shasdv005.infineon.com\CMU\CMU_ORCAD_CIS_LIB\CYPRESS_CIS_DATABASE\datasheet\RK73B1JTTD820J.pdf
R84 R85 = RES: RES, THK, 0402, 124 OHM, 1%, 63mW; Assembly Instructions: <Assembly Instructions>; CYPN: 500-91242-01; Enviromental: RoHS; FPLIST: RESC1005_IS0402Q,RESC1005_IS0402N; PART TYPE: THICK FILM; Size: 0402; Status: APPROVED; Tolerance: 1%; vendor_1: CYNTEC; vendor_2: VIKING TECH; vendor_3: Walsin; vendor_part_number_1: PFR05S-1240-FNH; vendor_part_number_2: CR-02FL6--124RAC; vendor_part_number_3: WR04X1240FTL; Datasheet: \\shasdv005.infineon.com\CMU\CMU_ORCAD_CIS_LIB\CYPRESS_CIS_DATABASE\datasheet\PFR05S-1240-FNH.pdf
U18 = TPD2EUSB30: DIO, TVS, ARRAY, ESD SUPPRESSOR, 2-CH, 8KV ESD, SOT3; Assembly Instructions: <Assembly Instructions>; CYPN: 530-90199-01; Enviromental: RoHS; PART TYPE: TVS; Status: APPROVED; vendor_1: Texas Instruments; Datasheet: \\shasdv005.infineon.com\CMU\CMU_ORCAD_CIS_LIB\CYPRESS_CIS_DATABASE\datasheet\TI_TPD2EUSB30ADRTR.pdf

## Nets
1.8V: R80.2 ; also on sheet 8 9 10
3.3V: C9.1 C10.1 C11.1 C12.1 C13.1 C14.1 C15.1 C16.1 R407.2 U1.1(VCC) U14.5(VDDA33_1) U14.10(VDDA33_2) U14.15(VDD33_1) U14.23(VDD33_2) U14.27(VBUS_DET) U14.29(VDDA33_3) U14.36(VDDA33_4) ; also on sheet 8 9 11
GND: C1.2 C2.2 C3.2 C4.2 C5.2 C6.2 C7.2 C8.2 C9.2 C10.2 C11.2 C12.2 C13.2 C14.2 C15.2 C16.2 C41.1 C55.2 C56.2 C59.2 C60.2 C61.2 C62.2 C63.2 C158.2 C159.2 C162.2 C165.2 C172.1 C173.2 C175.2 C180.1 D18.A(ANODE) D21.2 D24.A(ANODE) D29.A(ANODE) D32.A(ANODE) J1.A1(GND_1) J1.A12(GND_2) J1.B1(GND_3) J1.B12(GND_4) J3.4(GND1) J3.8(GND2) J4.4(GND1) J4.8(GND2) J46.1 J47.A1(GND_1) J47.A12(GND_2) J47.B1(GND_3) J47.B12(GND_4) Q14.S R2.2 R3.1 R4.2 R6.2 R7.2 R8.2 R10.2 R65.1 R84.2 R85.2 R360.1 R364.1 R366.1 R368.1 R372.1 R374.1 R404.1 U1.5(GND) U1.10(~{OE}) U2.2(GND) U14.H(HS-GND) U16.3(VSSD3) U16.13(VSSD2) U16.16(VSSD1) U16.17(VSSA) U16.H(HS-GND) U18.3(GND) U29.19(GND_1) U29.22(GND_2) U29.H(EPAD) U30.3(GND) U34.3(GND) U36.3(GND) U37.3(GND) U38.3(GND) U39.3(GND) Y1.2(GND) Y1.4(GND) ; also on sheet 8 9 10 11
GND_EARTH: C180.2 J1.SH1 J1.SH2 J1.SH3 J1.SH4 J3.SH1(SHIELD1) J3.SH2(SHIELD2) J3.SH3(SHIELD3) J3.SH4(SHIELD4) J4.SH1(SHIELD1) J4.SH2(SHIELD2) J4.SH3(SHIELD3) J4.SH4(SHIELD4) J47.SH1 J47.SH2 J47.SH3 J47.SH4 R372.2
V3P3: C162.1 C165.1 C173.1 R347.1 R359.1 R365.1 R367.1 R369.1 U29.23(VDDD)
VBUS: C2.1 C3.1 C4.1 C5.1 C6.1 J3.1(VBUS1) J3.5(VBUS2) J4.1(VBUS1) J4.5(VBUS2) U2.6(OUT)
VBUS_FET_EN: R297.2 TP32.1(TP) U29.3(VBUS_FET_EN)
VBUS_MAX: R366.2 R367.2 U29.2(VBUS_MAX)
VBUS_MIN: R364.2 R365.2 U29.1(VBUS_MIN)
VBUS_OUT: C139.1 U29.11(VDC_OUT) U35.5(D1_1) U35.6(D1_2) ; also on sheet 11
VCCD: C61.1 R94.1 U16.12(VCCD)
VCCD (page 09. Type-C BCR Controller): C175.1 U29.24(VCCD)
VDD_5V: C59.1 C60.1 U16.15(VBUS) ; also on sheet 9 11
VDDD: C62.1 C63.1 R80.1 R94.2 R407.1 U16.24(VDDD)
BT_USB_DN: J1.A7(DN1) J1.B7(DN2) U1.8(HSD2_N) U34.2(IN2)
BT_USB_DP: J1.A6(DP1) J1.B6(DP2) U1.9(HSD2_P) U34.1(IN1)
CC1: C158.1 D18.K(CATHODE) J47.A5(CC1) U29.15(CC1)
CC2: C159.1 D24.K(CATHODE) J47.B5(CC2) U29.14(CC2)
CTS: U16.22(CTS#) ; also on sheet 9
FAULT: Q14.G R374.2 TP31.1(TP) U29.9(FAULT)
FET_GATE: D25.A(ANODE) R298.2 R321.2 U35.2(G2) U35.4(G1)
FET_SRC: D25.C(CATHODE) R298.1 U35.1(S2) U35.3(S1)
FLIP: R347.2 TP35.1(TP) U29.10(FLIP)
HD1_M2_N: R92.1 ; also on sheet 10
HD1_M2_P: R93.1 ; also on sheet 10
HD1_N: R5.2 R92.2 U14.1(USBDM_DN1/PRT_DIS_M1)
HD1_P: R9.1 R93.2 U14.2(USBDP_DN1/PRT_DIS_P1)
HD1_PORT_N: J3.2(DM1) R5.1 U36.1(IN1)
HD1_PORT_P: J3.3(DP1) R9.2 U36.2(IN2)
HD2_N: J3.6(DM2) U14.3(USBDM_DN2/PRT_DIS_M2) U37.1(IN1)
HD2_P: J3.7(DP2) U14.4(USBDP_DN2/PRT_DIS_P2) U37.2(IN2)
HD3_N: J4.2(DM1) U14.6(USBDM_DN3/PRT_DIS_M3) U38.1(IN1)
HD3_P: J4.3(DP1) U14.7(USBDP_DN3/PRT_DIS_P3) U38.2(IN2)
HD4_N: J4.6(DM2) U14.8(USBDM_DN4/PRT_DIS_M4) U39.1(IN1)
HD4_P: J4.7(DP2) U14.9(USBDP_DN4/PRT_DIS_P4) U39.2(IN2)
ISNK_COARSE: R368.2 R369.2 U29.5(ISNK_COARSE)
ISNK_FINE: R359.2 R360.2 U29.6(ISNK_FINE)
nEXTRST: U14.26(~{RESET}) ; also on sheet 9
nOCS: U2.4(FLAG) U14.13(OCS_N1) U14.17(OCS_N2) U14.19(OCS_N3) U14.21(OCS_N4)
PERI_5V: C1.1 U2.1(IN) ; also on sheet 8 11
PWM0_0: R82.1 ; also on sheet 9
PWM0_1: R83.1 ; also on sheet 9
PWR1: U2.3(EN) U14.12(PRTPWR1/BC_EN1)
RTS: U16.21(RTS) ; also on sheet 9
RXD: U16.1(RXD) ; also on sheet 9
TXD: U16.23(TXD) ; also on sheet 9
USB2_N: U1.4(D_N) ; also on sheet 8
USB2_P: U1.3(D_P) ; also on sheet 8
USB-UART_VBUS: C144.1 C172.2 D21.1 D26.A(ANODE) J47.A4(VBUS_1) J47.A9(VBUS_2) J47.B4(VBUS_3) J47.B9(VBUS_4) R302.1 U29.18(VBUS_IN) U35.7(D2_1) U35.8(D2_2)
USB_PWR: C41.2 D29.K(CATHODE) D32.C(CATHODE) J1.A4(VBUS_1) J1.A9(VBUS_2) J1.B4(VBUS_3) J1.B9(VBUS_4) R1.1
USBOTG: R1.2 R2.1 U1.2(SEL) ; also on sheet 8
USBRPI_DM: J47.A7(DN1) J47.B7(DN2) U16.11(USBDM) U30.2(IN2)
USBRPI_DP: J47.A6(DP1) J47.B6(DP2) U16.10(USBDP) U30.1(IN1)
N17441828: R4.1 U2.5(ILIM)
N17442267: U1.7(HSD1_P) U14.31(USBDP_UP)
N17442276: U1.6(HSD1_N) U14.30(USBDM_UP)
N17442959: C8.1 U14.32(XTALOUT) Y1.3
N17443006: C7.1 U14.33(XTALIN/CLKIN) Y1.1
N17443696: R3.2 U14.35(RBIAS)
N17444208: R6.1 U14.24(SCL/SMBCLK/CFG_SEL0)
N17444213: R7.1 U14.22(SDA/SMBDATA/NON_REM1)
N17444218: R8.1 U14.28(SUSP_IND/LOCAL_PWR/NON_REM0)
N17444223: R10.1 U14.25(HS_IND/CFG_SEL1)
N17724540: C55.1 C57.1 R82.2 R85.1
N17724607: C56.1 C58.1 R83.2 R84.1
N17727243: C57.2 J46.3 U18.2(D-)
N17727252: C58.2 J46.2 U18.1(D+)
N17754557: TP33.1(TP) U29.7(HPI_INT)
N17754588: TP34.1(TP) U29.8(GPIO_1)
N17760781: C139.2 C144.2 R297.1 R302.2 R321.1
N17761001: Q14.D R373.1
N17761005: D26.C(CATHODE) R373.2
N17767575: J1.A5(CC1) R404.2
N17767581: J1.B5(CC2) R65.2
N17769646: TP37.1(TP) U29.12(HPI_SDA)
N17769649: TP36.1(TP) U29.13(HPI_SCL)

Not connected (* = marked no-connect by the designer): J1 A2(SSTXP1)* A3(SSTXN1)* A8(SBU1)* A10(SSRXN2)* A11(SSRXP2)* B2(SSTXP2)* B3(SSTXN2)* B8(SBU2)* B10(SSRX1N)* B11(SSRXP1)*; J46 4* 5* 6*; J47 A2(SSTXP1)* A3(SSTXN1)* A8(SBU1)* A10(SSRXN2)* A11(SSRXP2)* B2(SSTXP2)* B3(SSTXN2)* B8(SBU2)* B10(SSRX1N)* B11(SSRXP1)*; U14 11(TEST)* 14(CRFILT)* 16(PRTPWR2/BC_EN2)* 18(PRTPWR3/BC_EN3)* 20(PRTPWR4/BC_EN4)* 34(PLLFILT)*; U16 2(GPIO_7)* 4(TX_EN)* 5(GPIO_9)* 6(GPIO_10)* 7(POWER#)* 8(SUSPEND)* 9(WAKEUP)* 14(~{XRES})* 18(TXLED_0)* 19(RXLED_0)* 20(GPIO_2)*; U29 4(SAFE_PWR_EN) 16(D-) 17(D+) 20(DNU1) 21(DNU2)

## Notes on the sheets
sheet 1
- RPI DEBUG USB Type-C
- USB-UART Bridge
- Mount R407 , C61 and Remove R94
  while using GPIO_VREF=3.3V
- 3A Load Switch
- Fault LED
- NOTE:
- FAULT pin goes HIGH when
  (a) Power adapter does not advertise compatible
  PDOs
  (b) VBUS_DEV is out of (vbus_min, vbus_max)
  range
- CLAMP VGS to 10V ABSOLUTE
sheet 2
- USB Type-C BCR Controller
- VBUS Voltage Selectors: VBUS_MAX and VBUS_MIN
- Requested voltage = (VBUS_MIN -> VBUS_MAX)
  = 5V or 20V
- VBUS_MAX is decided by the Resistor options.
  Default VBUS_MAX is set to 20V
- VBUS_MIN is set to 5V
- VBUS_MIN and VBUS_MAX Resistor Options Table
- V3P3 RATIO
- 0/6
- 1/6
- 2/6
- 3/6
- >5/6
- VBUS_MAX, VBUS_MIN
- 5V
- 9V
- 12V
- 15V
- 20V
- PULLUP* (R365, R367)
- None
- 4.99K
- 4.99K
- 4.99K
- 0
- PULLDOWN* (R364, R366)
- 0
- 1K
- 2.4K
- 4.99K
- None
- I2C Slave Address: 0x08
- VBUS CURRENT SELECTORS: ISNK_COARSE and ISNK_FINE
- Requested (RDO) current = ISNK_COARSE + ISNK_FINE = 3000mA
- ISNK_COARSE and ISNK_FINE Resistor Options Table
- V3P3 RATIO
- 0/6
- 1/6
- 2/6
- 3/6
- 4/6
- >=5/6
- ISNK_COARSE
- 0A
- 1A
- 2A
- 3A
- 4A
- 5A
- ISNK_FINE
- 0mA
- 250mA
- 500mA
- 750mA
- 900mA
- PULLUP* (R359, R369)
- None
- 4.99K
- 4.99K
- 4.99K
- 4.99K
- 0
- PULLDOWN* (R360, R368)
- 0
- 1K
- 2.4K
- 4.99K
- 10K
- None
- ISNK_COARSE is set to 3A
- ISNK_FINE is set to 0mA
- *When pullup-pulldown combination is 0-none or none-0, use any resistor instead of 0-ohm
sheet 3
- Audio Out
sheet 4
- CYW9RPIM2BASE1
  M.2 WIFI BASEBOARD
- CONTENTS
- PAGE
- DESCRIPTION
- 01
- Title Page
- 02
- Block Diagram
- 03
- PMU Block Diagram
- 04
- USB
- 05
- CM4 HDMI & Fan Control
- 06
- CM4 GPIO & Ethernet
- 07
- M.2 Interface
- 08
- USB-UART Bridge
- 09
- Type-C BCR Controller
- 10
- Audio Out
- 11
- Power Supply
- 12
- GPIOs Mapping and Configuration
- 13
- Revision History
- Drawing Numbers
- PCBA
- PCB
- FAB DRW
- ASSY DRW
- SCH DRW
sheet 5
- Block Diagram
sheet 6
- Power Management Unit Block Diagram
sheet 7
- RPI Device-USB Connector
- USB 2.0 Hub
- If a cable is plugged into the uUSB socket the CM4 becomes a USB device
- Stacked USB connectors
- Current Limit switch
